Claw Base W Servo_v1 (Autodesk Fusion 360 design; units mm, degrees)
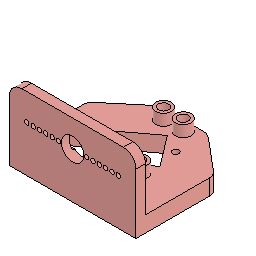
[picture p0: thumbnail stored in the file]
sketch "Sketch1" plane through (0, 0, 0) normal (0, 0, 1) x axis (1, 0, 0)
  line L1 (-20, -17.5) -> (20, -17.5)
  line L2 (-20, 17.5) -> (-20, -17.5)
  line L3 (20, 17.5) -> (-20, 17.5)
  line L4 (20, -17.5) -> (20, 17.5)
  line L5 (-20, 17.5) -> (20, -17.5)
  line L6 (20, 17.5) -> (-20, -17.5)
  line L7 (0, -17.5) -> (0, 17.5)
  line L8 (4.0769, -16) -> (-3.2529, -16)
  line L9 (-20, -17.5) -> (20, -17.5)
  line L10 (-20, -14.5) -> (-20, -17.5)
  line L11 (20, -14.5) -> (-20, -14.5)
  line L12 (20, -17.5) -> (20, -14.5)
  line L13 (-20, -14.5) -> (20, -17.5)
  line L14 (20, -14.5) -> (-20, -17.5)
  line L15 (7.7, -17.5) -> (7.7, 17.5)
  line L16 (-7.7, -17.5) -> (-7.7, 17.5)
  line L17 (20, 14.33) -> (-20, 14.33)
  line L18 (20, -4) -> (-20, -4)
  line L19 (-7.0975, -14.7693) -> (-16.1328, -2.7791)
  line L20 (-7.1761, 3.9702) -> (-16.1328, -2.7791)
  line L21 (-8.6616, -12.6938) -> (-16.1328, -2.7791)
  line L22 (-8.8508, -12.4426) -> (-16.1328, -2.7791)
  line L23 (9.0386, 1.038) -> (-8.8508, -12.4426)
  line L24 (1.7566, 10.7015) -> (9.0386, 1.038)
  line L25 (-16.1328, -2.7791) -> (1.7566, 10.7015)
  line L26 (12.5021, 11.2234) -> (5.3976, 5.8698)
  line L27 (-16.1516, -10.3687) -> (-12.4918, -7.6109)
  line L28 (-20, 7.1791) -> (-7.7, 17.5)
  line L29 (8.3565, 17.5) -> (-7.7, 17.5)
  line L30 (20.0608, 7.1281) -> (7.7, 17.5)
  line L31 (23.8359, 17.5) -> (7.7, 17.5)
  circle C1 centre (7.7, -4) radius 1.6
  circle C2 centre (7.7, -4) radius 7.7
  circle C3 centre (-7.7, -4) radius 7.7
  circle C4 centre (-3.1, 14.33) radius 1.6
  circle C5 centre (3.1, 14.33) radius 1.6
  circle C6 centre (7.7, -4) radius 2.5
  circle C7 centre (7.5539, 7.4947) radius 1
  circle C8 centre (-14.6481, -9.2358) radius 1
  point P6 (0, 0)
  point P1 (0, 0)
  point P7 (0, 17.5)
  point P8 (0, -17.5)
  point P15 (0, -16)
  point P16 (7.7, 17.5)
  point P17 (7.7, -17.5)
  point P18 (-7.7, 17.5)
  point P19 (-7.7, -17.5)
  point P20 (-20, 14.33)
  point P21 (20, 14.33)
  point P22 (-20, -4)
  point P23 (20, -4)
  point P24 (7.7, -4)
  point P26 (-7.7, -4)
  point P27 (-3.1, 14.33)
  point P37 (5.3976, 5.8698)
  point P39 (7.5539, 7.4947)
  point P40 (-12.4918, -7.6109)
  point P42 (-14.6481, -9.2358)
  point P43 (-20, 7.1791)
  point P4 (-20, 17.5)
  point P5 (20, 17.5)
  point P3 (-20, -17.5)
  point P12 (-20, -17.5)
  point P13 (-20, -14.5)
  point P14 (20, -14.5)
  point P30 (-16.1328, -2.7791)
  point P36 (1.7566, 10.7015)
  horizontal L1
  perpendicular L1 L2
  parallel L1 L3
  parallel L2 L4
  coincident L5 P6
  coincident L6 P6
  coincident P1 P6
  midpoint L3 P7
  midpoint L1 P8
  horizontal L8
  horizontal L9
  perpendicular L9 L10
  parallel L9 L11
  parallel L10 L12
  coincident L13 P15
  coincident L14 P15
  coincident L8 P15
  coincident L7 P15
  coincident L3 P16
  coincident L9 P17
  perpendicular L9 L15
  coincident L3 P18
  coincident L9 P19
  perpendicular L9 L16
  coincident L2 P20
  coincident L4 P21
  perpendicular L4 L17
  coincident L2 P22
  coincident L4 P23
  perpendicular L4 L18
  coincident L18 P24
  coincident L15 P24
  concentric C1 C2
  coincident L18 P26
  coincident L16 P26
  coincident L17 P27
  symmetric L7 C4 C5
  concentric C1 C6
  perpendicular L19 L20
  perpendicular L20 L21
  perpendicular L22 L23
  parallel L22 L24
  parallel L23 L25
  perpendicular L20 L22
  midpoint L24 P37
  perpendicular L24 L26
  coincident L26 P39
  midpoint L22 P40
  perpendicular L21 L27
  coincident L27 P42
  horizontal L29
  coincident L2 P43
  horizontal L31
  dimension "d1" distance P4 P5 = 40
  dimension "d2" distance P3 P4 = 35
  dimension "d3" distance L1 L8 = 1.5
  dimension "d5" distance P12 P13 = 3
  dimension "d6" distance L7 L15 = 7.7 (= "( 15.4 / 2 ) * 1 mm")
  dimension "d7" distance L7 L16 = 7.7 (= "d6")
  dimension "d14" distance L11 L18 = 10.5
  dimension "d15" diameter C1 = 3.2
  dimension "d16" diameter C2 = 15.4
  dimension "d17" diameter C3 = 15.4
  dimension "d18" distance L17 L18 = 18.33
  dimension "d29" diameter C4 = 3.2
  dimension "d30" distance L7 P27 = 3.1
  dimension "d42" distance P13 P14 = 40 (= "d1")
  dimension "d49" diameter C6 = 5
  dimension "d68" angle L18 L19 = 127 (= "180 deg - 53 deg")
  dimension "d69" distance P26 L19 = 6
  dimension "d70" distance P26 L20 = 6.05 (= "( 12.10 / 2 ) * 1 mm")
  dimension "d79" distance P30 P36 = 22.4
  dimension "d81" diameter C7 = 2 (= "d87")
  dimension "d82" distance L24 P39 = 2.7 (= "d88")
  dimension "d87" diameter C8 = 2
  dimension "d88" distance L19 P42 = 2.7 (= "4.7 mm + 0.3 mm - 2.3 mm")
  dimension "d89" angle L28 L29 = 140
  dimension "d90" angle L30 L31 = 40
extrude "Extrude1" new body sketch "Sketch1" profile of L2 L3 L4 L11 C1 C4 C5 C6 L21 L22 L23 L24 L25 C7 C8 L28 L30 along normal blind 5
extrude "Extrude2" add sketch "Sketch1" profile of L1 L2 L4 L9 L10 L11 L12 along normal blind 23 (= "3 mm + 20 mm")
sketch "Sketch3" plane through (0, 0, 5) normal (0, 0, 1) x axis (-1, 0, 0)
  line L1 (20, 14.5) -> (20, -7.1791)
  line L2 (-20, -7.1791) -> (-20, 14.5)
  line L3 (7.7, -17.5) -> (-7.7, -17.5)
  line L4 (-1.7566, -10.7015) -> (16.1328, 2.7791)
  line L5 (-9.0386, -1.038) -> (-1.7566, -10.7015)
  line L6 (8.8508, 12.4426) -> (-9.0386, -1.038)
  line L7 (16.1328, 2.7791) -> (8.8508, 12.4426)
  line L8 (20, -7.1791) -> (7.7, -17.5)
  line L9 (-7.7, -17.5) -> (-20, -7.1791)
  line L10 (-20, 14.5) -> (20, 14.5)
  circle C1 centre (-7.7, 4) radius 1.6
  circle C2 centre (-3.1, -14.33) radius 1.6
  circle C3 centre (3.1, -14.33) radius 1.6
  circle C4 centre (-7.7, 4) radius 2.5
  circle C5 centre (-3.1, -14.33) radius 2.5
  circle C6 centre (3.1, -14.33) radius 2.5
  circle C7 centre (-7.5539, -7.4947) radius 1
  circle C8 centre (14.6481, 9.2358) radius 1
  concentric C1 C4
  concentric C2 C5
  concentric C3 C6
  dimension "d50" diameter C4 = 5
  dimension "d53" diameter C5 = 5
  dimension "d54" diameter C6 = 5
extrude "Extrude3" add sketch "Sketch3" profile of C1 C2 C3 C4 C5 C6 along normal blind 3.55 (= "2.55 mm + 1 mm")
fillet "Fillet2" radius 4
fillet "Fillet3" radius 3
sketch "Sketch4" plane through (0, -14.5, 0) normal (0, 1, 0) x axis (-1, 0, 0)
  line L1 (20, 23) -> (20, 5)
  line L2 (-20, 23) -> (20, 23)
  line L3 (-20, 5) -> (-20, 23)
  line L4 (20, 14.5) -> (-20, 14.5)
  line L5 (0, 10.3228) -> (0, 23)
  line L6 (-14.1597, 16.5073) -> (-2.3255, 17.1822)
  line L7 (14.1598, 12.4909) -> (2.3257, 11.8179)
  line L8 (2.3255, 17.1823) -> (14.1599, 16.5114)
  line L9 (-2.3256, 11.8178) -> (-14.16, 12.4861)
  line L10 (20, 5) -> (-20, 5)
  arc A1 centre (14.0502, 14.5011) radius 2.0132 clockwise from (14.1599, 16.5114) to (14.1598, 12.4909)
  arc A2 centre (-14.0513, 14.4967) radius 2.0135 clockwise from (-14.16, 12.4861) to (-14.1597, 16.5073)
  circle C1 centre (0, 14.5) radius 2.3
  circle C2 centre (0, 14.5) radius 3.55
  circle C3 centre (-4.45, 14.5) radius 0.7
  circle C4 centre (-6.45, 14.5) radius 0.7
  circle C5 centre (-8.45, 14.5) radius 0.7
  circle C6 centre (-10.45, 14.5) radius 0.7
  circle C7 centre (-12.45, 14.5) radius 0.7
  circle C8 centre (-14.45, 14.5) radius 0.7
  point P6 (-20, 14.5)
  point P7 (20, 14.5)
  point P8 (0, 23)
  point P13 (0, 14.5)
  point P18 (0, 14.5)
  point P19 (2.3255, 17.1823)
  point P20 (-2.3255, 17.1822)
  point P21 (-2.3256, 11.8178)
  point P22 (2.3257, 11.8179)
  point P23 (-4.45, 14.5)
  point P14 (0, 14.5)
  coincident L3 P6
  coincident L1 P7
  perpendicular L1 L4
  midpoint L2 P8
  perpendicular L4 L5
  coincident P13 P18
  coincident C2 P19
  coincident C2 P20
  coincident C2 P21
  coincident C2 P22
  coincident L4 P23
  dimension "d95" distance L2 L4 = 8.5 (= "( 17 / 2 ) * 1 mm")
  dimension "d125" diameter C2 = 7.1
  dimension "d128" diameter C3 = 1.4
  dimension "d129" distance P14 P23 = 4.45
  dimension "d132" R-Pattern1-uDistance = -10
  dimension "d133" R-Pattern1-vDistance = 0
fillet "Fillet4" radius 4
extrude "Extrude7" cut sketch "Sketch4" profile of L6 A1 L7 A2 L8 L9 C2 C3 C4 C5 C6 C7 C8 against normal blind 0.6
extrude "Extrude8" cut sketch "Sketch4" profile of L6 L7 C1 L8 L9 C2 against normal blind 3
extrude "Extrude9" cut sketch "Sketch4" profile of C3 C4 C5 C6 C7 C8 against normal blind 3
mirror "Mirror1" mirrorStitchTolerance 0.1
